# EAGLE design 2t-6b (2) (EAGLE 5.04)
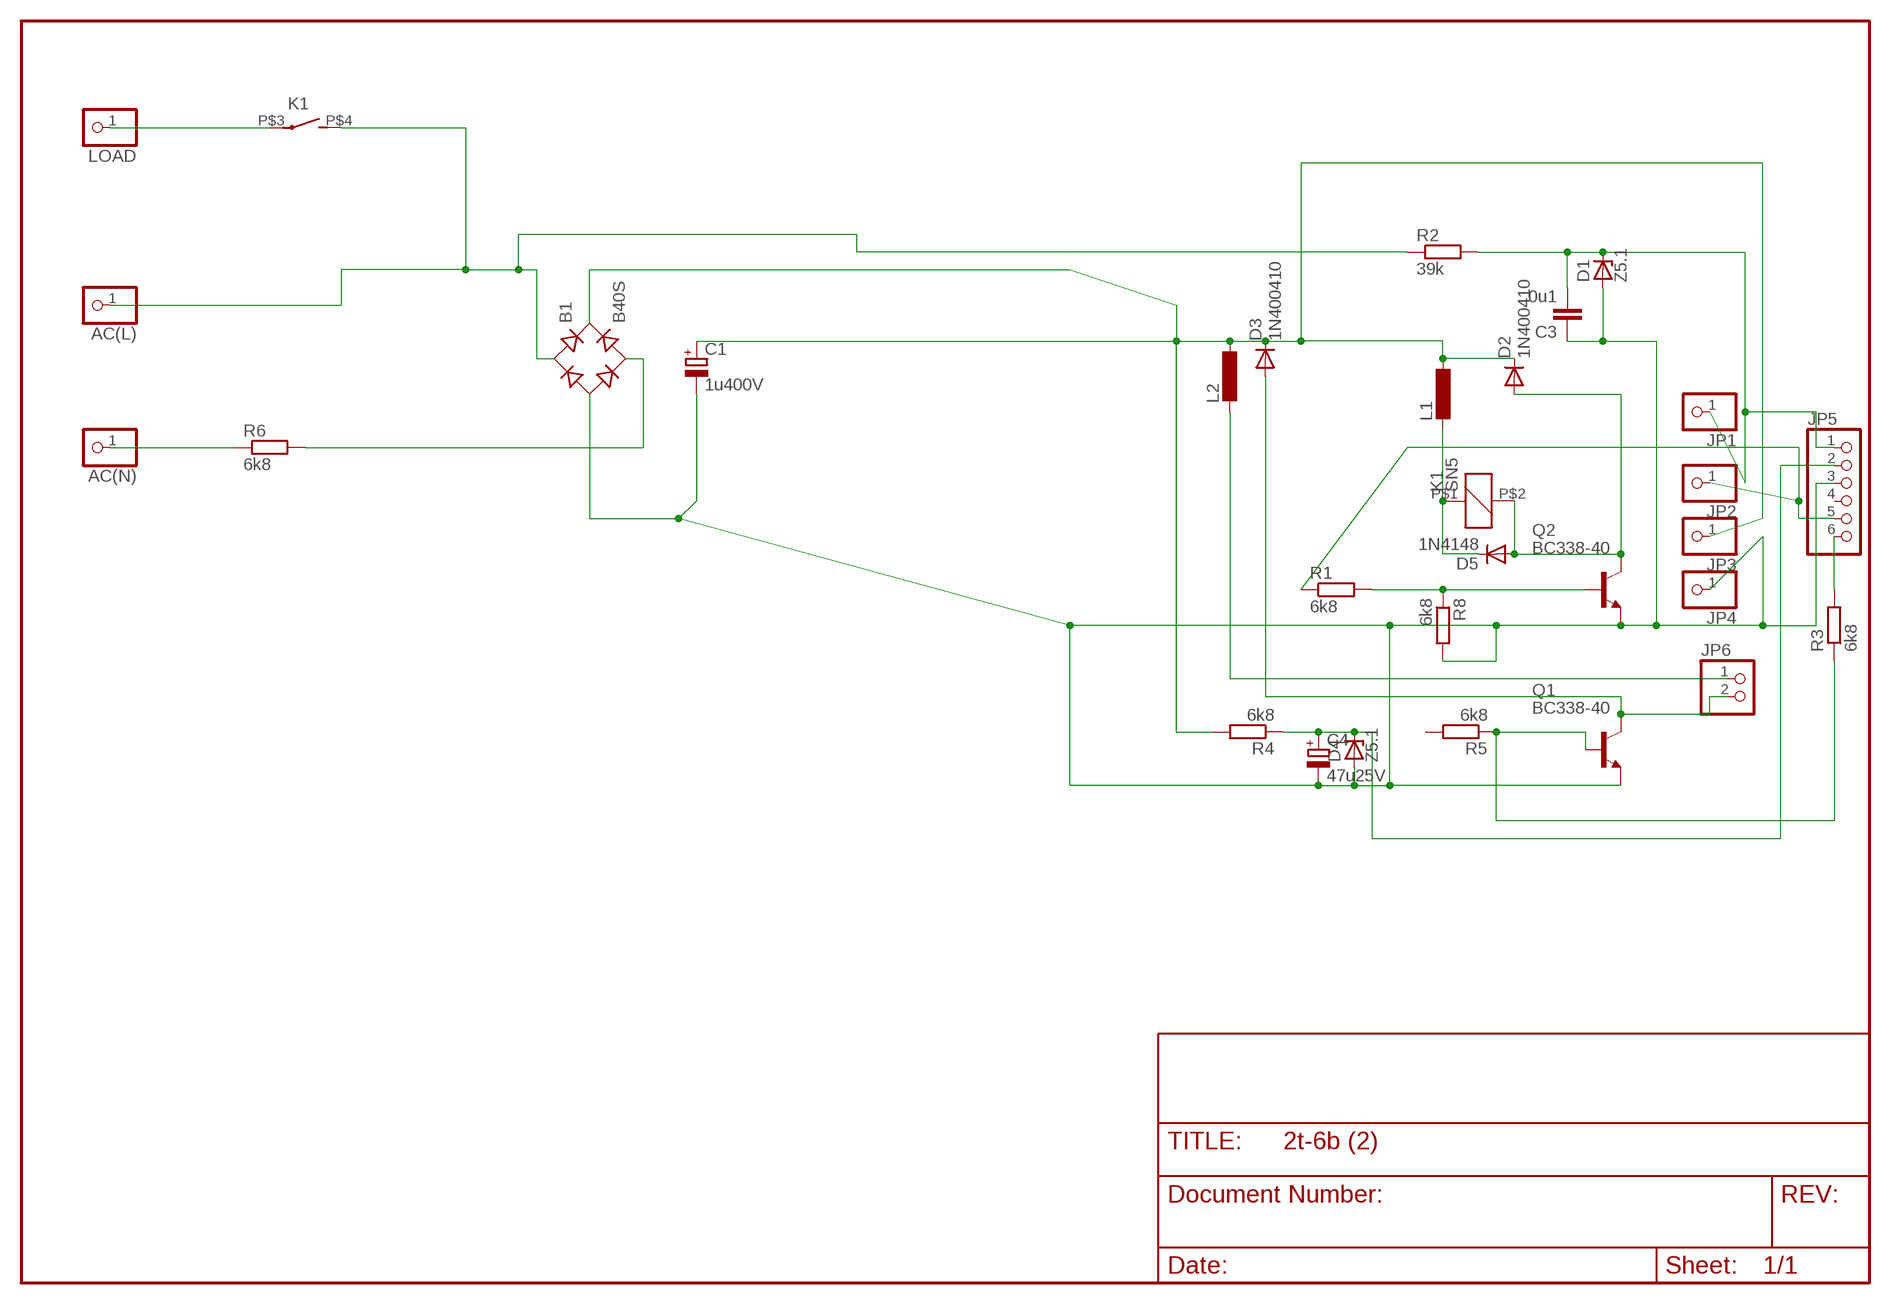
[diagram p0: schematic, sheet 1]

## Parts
AC(L)  PINHD-1X1  [1X01]
AC(N)  PINHD-1X1  [1X01]
B1  B40S  RECTIFIER-B40S  [B40S]
C1  1u400V  CPOL-EUE2.5-5  [E2,5-5]
C3  0u1  C-EUC0805  [C0805]
C4  47u25V  CPOL-EUE2.5-5  [E2,5-5]
D1  Z5.1  ZENER-DIODESOT23  [SOT23]
D2  1N400410  [DO41-10]
D3  1N400410  [DO41-10]
D4  Z5.1  ZENER-DIODESOT23  [SOT23]
D5  1N4148  1N4148MINIMELF  [MINIMELF]
JP1  PINHD-1X1  [1X01]
JP2  PINHD-1X1  [1X01]
JP3  PINHD-1X1  [1X01]
JP4  PINHD-1X1  [1X01]
JP5  PINHD-1X6  [1X06]
JP6  PINHD-1X2  [1X02]
K1  SN5  [HU]
L1  L-EU0207/5V  [0207/5V]
L2  L-EU0207/5V  [0207/5V]
LOAD  PINHD-1X1  [1X01]
Q1  BC338-40  [TO92-EBC]
Q2  BC338-40  [TO92-EBC]
R1  6k8  R-EU_R0805  [R0805]
R2  39k  R-EU_0204/2V  [0204V]
R3  6k8  R-EU_R0805  [R0805]
R4  6k8  R-EU_0204/5  [0204/5]
R5  6k8  R-EU_R0805  [R0805]
R6  6k8  R-EU_0204/2V  [0204V]
R8  6k8  R-EU_R0805  [R0805]

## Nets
AC1: B1.AC2 R6.2
N$1: AC(L).1 B1.AC1 K1.P$4(2:S) R2.1
N$2: B1.+ C1.+ D2.C D3.C JP3.1 L1.1 L2.1 R4.2
N$4: K1.P$3(2:P) LOAD.1
N$5: C3.2 D1.3(C) JP1.1 JP5.1 R2.2
N$6: C4.+ D4.3(C) JP5.2 R4.1
N$7: Q1.B R3.1 R5.1
N$8: D3.A JP6.2 Q1.C
N$9: JP5.6 R3.2
N$10: Q2.B R1.2 R8.1
N$11: D2.A D5.A K1.P$2 Q2.C
N$12: JP2.1 JP5.5 R1.1
N$13: AC(N).1 R6.1
N$14: D5.C K1.P$1 L1.2
N$15: JP6.1 L2.2
V-: B1.- C1.- C3.1 C4.- D1.1(A) D4.1(A) JP4.1 JP5.3 Q1.E Q2.E R8.2
Unconnected: JP5.4 R5.2

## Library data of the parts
AC(L) AC(N) LOAD = pinhead(2):PINHD-1X1: PIN HEADER
B1 = rectifier:RECTIFIER-: Rectifier
C1 C4 = rcl-2:CPOL-EU: POLARIZED CAPACITOR, European symbol
C3 = rcl-2:C-EU: CAPACITOR, European symbol
D1 D4 = diode-1:ZENER-DIODE: Z-Diode
D2 D3 = diode-1:1N4004: DIODE
D5 = diode-1:1N4148: DIODE
JP1-JP4 = pinhead:PINHD-1X1: PIN HEADER
JP5 = pinhead:PINHD-1X6: PIN HEADER
JP6 = pinhead:PINHD-1X2: PIN HEADER
K1 = relay:SN*: Slim PCB Relay 1 pole 6 A SCHRACK Source: http://www.schrack.com/.. 5815.pdf
L1 L2 = rcl-2:L-EU: INDUCTOR, European symbol
Q1 Q2 = transistor-npn:BC338*: NPN Transistor
R1-R6 R8 = rcl-2:R-EU_: RESISTOR, European symbol

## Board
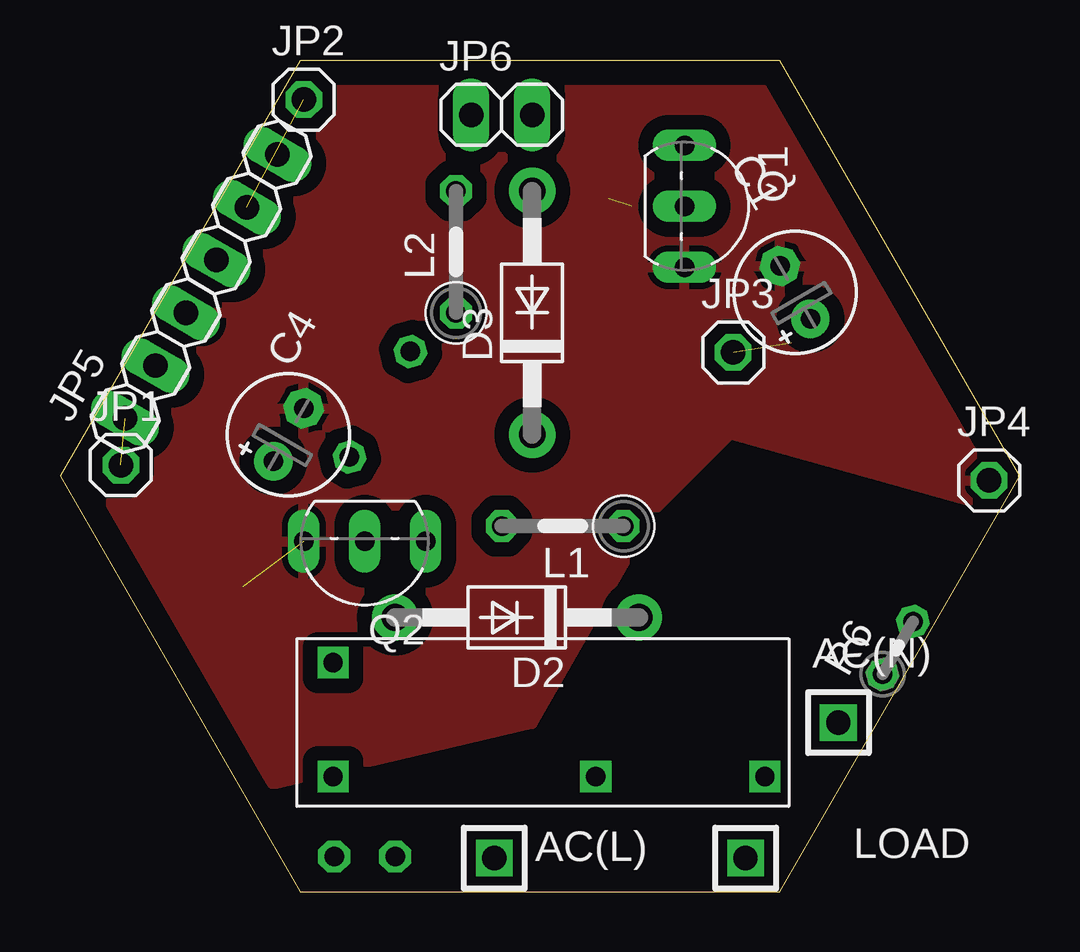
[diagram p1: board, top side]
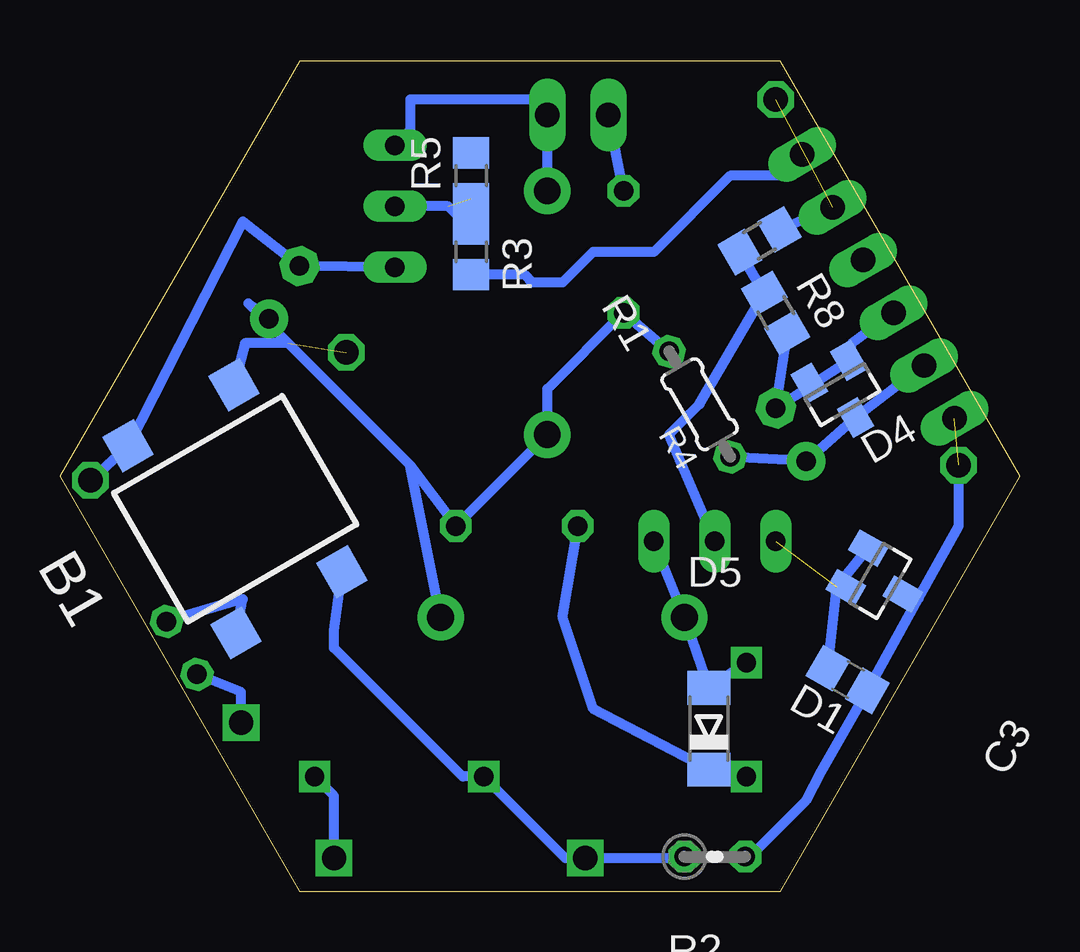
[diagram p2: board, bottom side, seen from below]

Size 40 x 34.64 mm. Coordinates in mm from the lower left corner, seen from the top.
Outline: 10,0 30,0 40,17.32 30,34.64 10,34.64 0,17.32 10,0
Copper layers (1*16): Top 0.035mm / dielectric 1.5mm / Bottom 0.035mm
Design rules "default": minimum track width 10mil, minimum drill 24mil, track to track 8mil, track to pad 8mil, pad to pad 8mil, via to via 8mil, smd to smd 8mil, copper to edge 40mil, drill to drill 8mil, minimum pad ring 10mil, minimum via ring 8mil, stop-mask expansion 4mil, vias tented up to drill 0mil, thermal gap 10mil

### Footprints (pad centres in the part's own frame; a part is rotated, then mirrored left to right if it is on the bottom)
1X01 = drill 1.016 square: 1 0,0
B40S = smd 1.5 x 1.7: + -2.55,-4.5; - 2.55,-4.5; AC1 -2.55,4.5; AC2 2.55,4.5
E2,5-5 = drill 0.813 pad 1.6 round: + -1.27,0 | drill 0.813 pad 1.6 octagon: - 1.27,0
C0805 = smd 1.3 x 1.5: 1 -0.95,0; 2 0.95,0
SOT23 = smd 1 x 1.4: 1 -0.95,-1.1; 2 0.95,-1.1; 3 0,1.1
DO41-10 = drill 1.118 pad 1.93 round: A 5.08,0; C -5.08,0
MINIMELF = smd 1.4 x 1.8: A 1.7,0; C -1.7,0
1X01' = drill 1.016 octagon: 1 0,0
1X06 = drill 1.016 long: 1 -6.35,0; 2 -3.81,0; 3 -1.27,0; 4 1.27,0; 5 3.81,0; 6 6.35,0
1X02 = drill 1.016 long: 1 -1.27,0; 2 1.27,0
HU = drill 0.8 square: P$1 2.25,-9; P$2 -2.5,-9; P$3 2.25,9; P$4 2.25,1.95
0207/5V = drill 0.813 octagon: 1 -2.54,0; 2 2.54,0
TO92-EBC = drill 0.813 long: B 0,-1.27; C -2.54,-1.27; E 2.54,-1.27
R0805 = smd 1.3 x 1.5: 1 -0.95,0; 2 0.95,0
0204V = drill 0.813 octagon: 1 -1.27,0; 2 1.27,0
0204/5 = drill 0.813 octagon: 1 -2.54,0; 2 2.54,0

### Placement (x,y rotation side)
AC(L)  18.1,1.4 0 top
AC(N)  32.45,7.05 0 top
B1  32.7,15.96 210 bottom
C1  30.65,24.98 120 top
C3  7.16,8.84 330 bottom
C4  9.53,19.05 60 top
D1  5.81,12.95 240 bottom
D2  19.05,11.43 180 top
D3  19.68,24.13 90 top
D4  7.39,20.72 210 bottom
D5  12.95,6.79 90 bottom
JP1  [1X01']  2.54,17.78 0 top
JP2  [1X01']  10.16,33.02 0 top
JP3  [1X01']  28.07,22.48 0 top
JP4  [1X01']  38.73,17.14 0 top
JP5  5.89,25.23 60 top
JP6  18.41,32.38 0 top
K1  20.38,7.05 270 top
L1  20.95,15.24 180 top
L2  16.51,26.67 90 top
LOAD  28.57,1.4 0 top
Q1  27.3,28.57 270 top
Q2  12.7,13.34 180 top
R1  10.84,27.13 210 bottom
R2  12.7,1.46 0 bottom
R3  22.86,26.67 270 bottom
R4  13.34,20.32 120 bottom
R5  22.86,29.84 90 bottom
R6  34.92,10.16 60 top
R8  10.16,24.13 300 bottom

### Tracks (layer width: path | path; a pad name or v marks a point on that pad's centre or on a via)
AC1
  Bottom 0.406: R6.2 32.38,12.2 B1.AC2
N$1
  Bottom 0.406: R2.1 14.03,1.4 AC(L).1 18.93,1.4 K1.P$4 23.21,4.8 28.57,10.16 28.57,10.89 B1.AC1
N$2  (1 unrouted)
  Bottom 0.406: D2.C 25.4,17.78 | 25.4,17.78 30.48,22.86 | 30.48,22.86 32.29,22.86 B1.+ | 25.4,17.78 L1.1 D3.C 19.68,20.95 L2.1 R4.2 | C1.+ 32.14,24.52 30.48,22.86
N$4
  Bottom 0.406: LOAD.1 28.57,3.99 K1.P$3
N$5  (1 unrouted)
  Bottom 0.406: R2.2 11.24,1.46 8.89,3.81 8.26,5.02 C3.2 4.21,12.22 | 4.21,12.22 2.54,15.24 JP1.1 | 4.21,12.22 D1.3
N$6
  Bottom 0.406: JP5.2 4.45,21.59 D4.3 C4.+ R4.1
N$7  (1 unrouted)
  Bottom 0.406: Q1.B 23.82,28.57 R3.1
N$8
  Bottom 0.406: Q1.C 25.4,31.75 25.4,33.02 20.32,33.02 JP6.2 D3.A
N$9
  Bottom 0.406: R3.2 20.64,25.72 20.32,25.4 19.05,25.4 17.78,26.67 15.24,26.67 12.06,29.84 9.94,29.84 JP5.6
N$10
  Bottom 0.406: Q2.B 14.61,19.05 13.34,20.32 R8.1 R1.2
N$11
  Bottom 0.406: K1.P$2 D5.A D2.A Q2.C
N$12  (1 unrouted)
  Bottom 0.406: R1.1 JP5.5
N$13
  Bottom 0.406: AC(N).1 32.45,8.32 R6.1
N$14
  Bottom 0.406: K1.P$1 D5.C 17.78,7.62 19.05,11.43 L1.2
N$15
  Bottom 0.406: L2.2 JP6.1
V-  (1 unrouted)
  Bottom 0.406: JP5.3 6.99,22.86 D4.1 C4.- R8.2 | C3.1 7.62,12.7 D1.1 | JP4.1 B1.- 32.38,27.94 C1.- Q1.E
  pour Top (isolate 0.61, rank 5): 39.37,15.88 27.94,19.05 24.77,15.88 19.68,6.99 8.89,4.45 1.91,15.88 11.43,33.66 29.84,34.29 38.73,19.68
